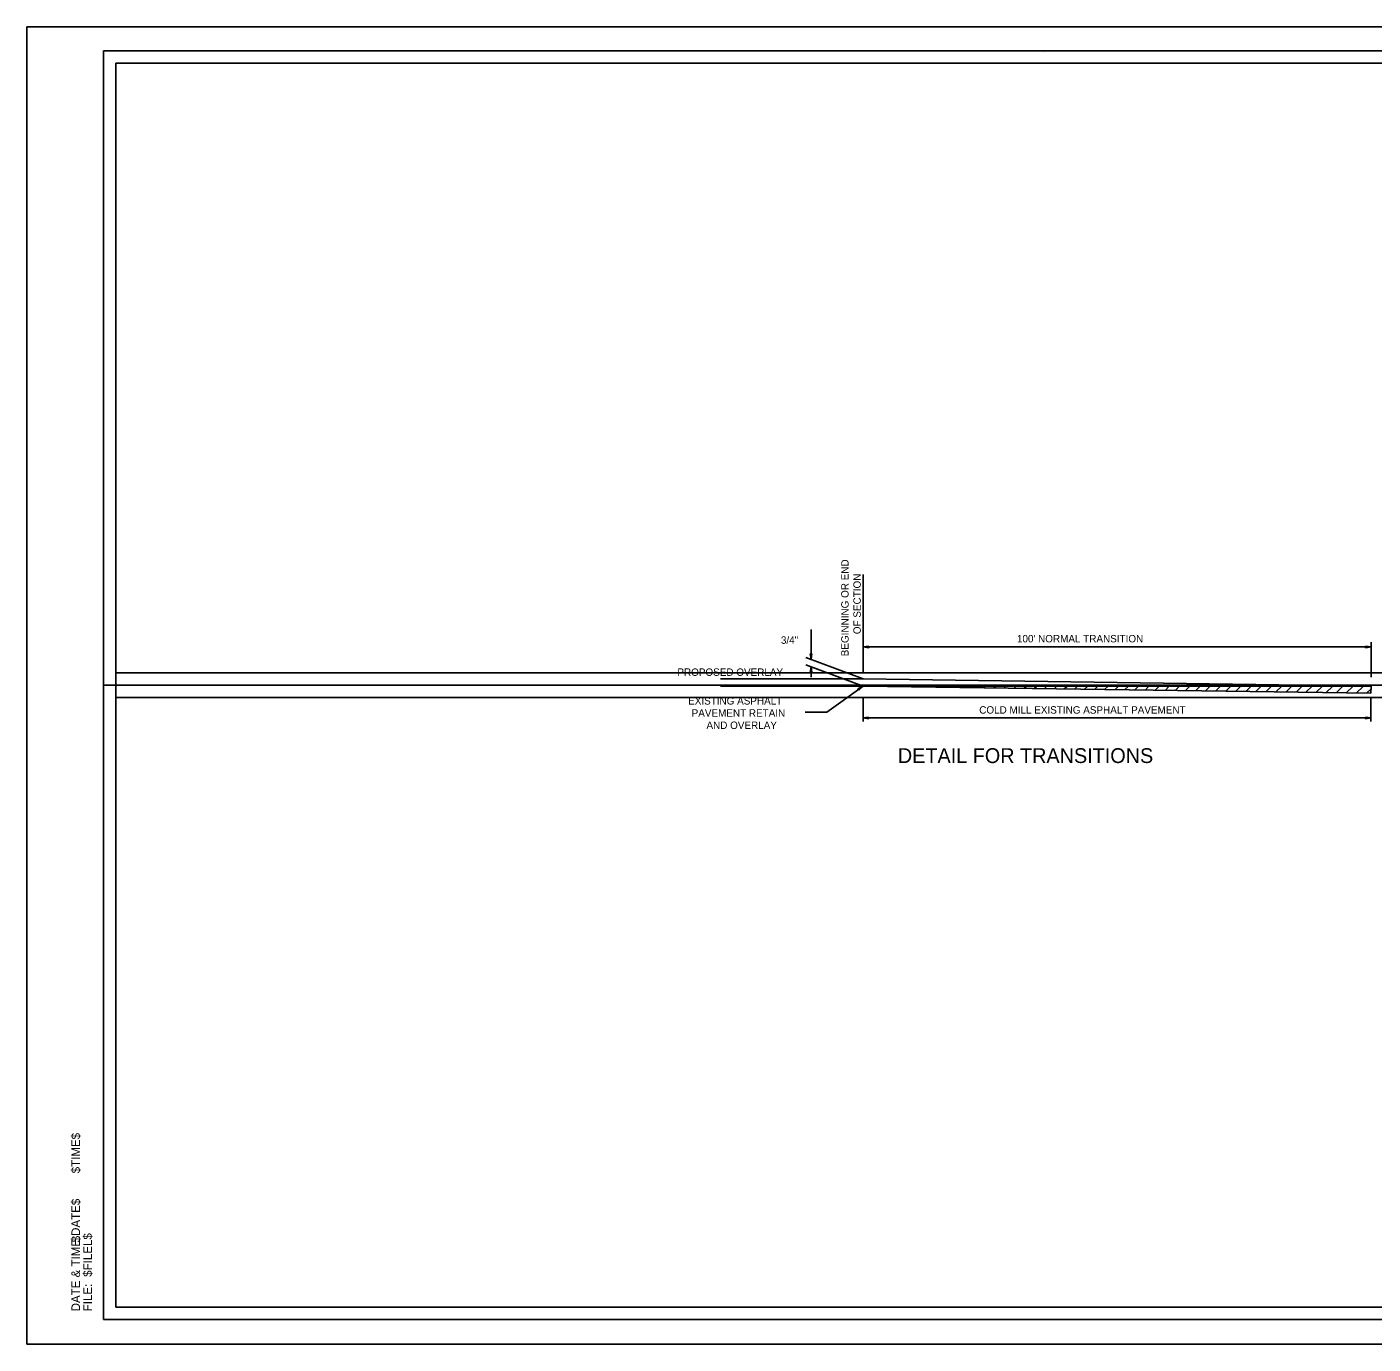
# Model space of a CAD drawing. Extents: x -12 to 321, y -4 to 209.
# Drawn here: x -12.4 to 205.7, y -4 to 209.4 of the extents above; entities that cross this region are included whole.
import ezdxf

# ---------------------------------------------------------------- set-up
doc = ezdxf.new("R2010")
doc.units = 0
for name, color, linetype in [('Default', 7, 'Continuous'), ('R_Border', 7, 'Continuous'), ('R_Border Notes', 7, 'Continuous'), ('R_Border Plan-Plan', 7, 'Continuous'), ('R_No Plot', 7, 'Continuous')]:
    doc.layers.add(name, color=color, linetype=linetype)

msp = doc.modelspace()

# ---------------------------------------------------------------- linework, layer by layer
at = {"layer": 'Default'}
for p, q in [((123.07, 104.67), (123.07, 120.64)), ((114.63, 106.94), (114.63, 111.74)), ((124, 109.07), (123.07, 108.94)), ((124, 108.8), (124, 109.07)), ((204.44, 109.07), (205.38, 108.94)), ((204.44, 109.07), (204.44, 108.8)), ((205.38, 104.05), (205.38, 109.73)), ((123.07, 103.74), (113.79, 107.2)), ((114.5, 107.83), (114.63, 106.94)), ((114.5, 107.83), (114.63, 107.07)), ((114.76, 107.83), (114.5, 107.83)), ((114.54, 107.83), (114.63, 107.25)), ((114.54, 107.83), (114.63, 107.38)), ((114.59, 107.83), (114.63, 107.56)), ((114.59, 107.83), (114.63, 107.69)), ((114.76, 107.83), (114.63, 106.94)), ((114.67, 107.83), (114.63, 107.56)), ((114.72, 107.83), (114.63, 107.25)), ((114.72, 107.83), (114.63, 107.07)), ((114.67, 107.83), (114.63, 107.38)), ((114.63, 107.83), (114.63, 107.69)), ((123.07, 108.94), (205.38, 108.94)), ((124, 108.8), (123.07, 108.94)), ((124, 109.03), (123.2, 108.94)), ((124, 108.8), (123.2, 108.94)), ((124, 109.03), (123.38, 108.94)), ((124, 108.85), (123.38, 108.94)), ((124, 108.98), (123.56, 108.94)), ((124, 108.85), (123.56, 108.94)), ((124, 108.98), (123.69, 108.94)), ((124, 108.89), (123.69, 108.94)), ((124, 108.94), (123.87, 108.94)), ((124, 108.89), (123.87, 108.94)), ((204.44, 109.03), (205.07, 108.94)), ((204.44, 109.03), (205.2, 108.94)), ((204.44, 108.98), (204.76, 108.94)), ((204.44, 108.98), (204.89, 108.94)), ((204.44, 108.8), (205.38, 108.94)), ((204.44, 108.89), (204.76, 108.94)), ((204.44, 108.85), (205.07, 108.94)), ((204.44, 108.8), (205.2, 108.94)), ((204.44, 108.85), (204.89, 108.94)), ((204.44, 108.89), (204.58, 108.94)), ((204.44, 108.94), (204.58, 108.94)), ((123.07, 102.59), (113.79, 106.05)), ((114.5, 104.8), (114.63, 105.74)), ((114.5, 104.8), (114.63, 105.6)), ((114.5, 104.8), (114.76, 104.8)), ((114.54, 104.8), (114.63, 105.43)), ((114.54, 104.8), (114.63, 105.3)), ((114.59, 104.8), (114.63, 105.12)), ((114.59, 104.8), (114.63, 104.94)), ((114.76, 104.8), (114.63, 105.74)), ((114.63, 104.05), (114.63, 105.74)), ((114.72, 104.8), (114.63, 105.6)), ((114.72, 104.8), (114.63, 105.43)), ((114.67, 104.8), (114.63, 105.3)), ((114.67, 104.8), (114.63, 105.12)), ((114.63, 104.8), (114.63, 104.94)), ((99.97, 103.74), (123.07, 103.74)), ((99.97, 102.58), (205.38, 102.58)), ((117.21, 98.37), (123.07, 102.59)), ((122.23, 102.14), (123.07, 102.59)), ((122.4, 101.92), (123.07, 102.59)), ((205.38, 102.59), (123.07, 103.74)), ((205.33, 101.43), (123.07, 102.59)), ((126.31, 102.54), (126.36, 102.59)), ((127.93, 102.52), (128, 102.59)), ((129.55, 102.49), (129.69, 102.59)), ((131.21, 102.47), (131.33, 102.59)), ((132.84, 102.45), (132.97, 102.59)), ((134.46, 102.42), (134.62, 102.59)), ((136.08, 102.4), (136.26, 102.59)), ((137.74, 102.38), (137.95, 102.59)), ((139.36, 102.36), (139.59, 102.59)), ((141.03, 102.33), (141.24, 102.59)), ((142.61, 102.31), (142.88, 102.59)), ((144.27, 102.29), (144.57, 102.59)), ((145.89, 102.26), (146.21, 102.59)), ((147.55, 102.24), (147.86, 102.59)), ((149.13, 102.22), (149.54, 102.59)), ((150.8, 102.2), (151.19, 102.59)), ((152.42, 102.17), (152.83, 102.59)), ((154.04, 102.15), (154.48, 102.58)), ((155.66, 102.13), (156.16, 102.59)), ((157.33, 102.1), (157.8, 102.59)), ((158.95, 102.08), (159.45, 102.59)), ((160.57, 102.06), (161.09, 102.59)), ((162.19, 102.04), (162.78, 102.59)), ((163.85, 102.01), (164.42, 102.59)), ((165.43, 101.99), (166.07, 102.59)), ((167.09, 101.97), (167.71, 102.59)), ((168.76, 101.94), (169.35, 102.59)), ((170.38, 101.92), (171.04, 102.59)), ((172, 101.9), (172.68, 102.59)), ((173.62, 101.87), (174.33, 102.59)), ((175.29, 101.85), (176.02, 102.59)), ((176.91, 101.83), (177.66, 102.59)), ((178.53, 101.8), (179.3, 102.59)), ((180.15, 101.78), (180.95, 102.59)), ((181.81, 101.76), (182.63, 102.59)), ((183.39, 101.74), (184.28, 102.59)), ((185.05, 101.71), (185.92, 102.59)), ((186.68, 101.69), (187.57, 102.59)), ((188.34, 101.67), (189.21, 102.59)), ((189.91, 101.64), (190.9, 102.59)), ((191.58, 101.62), (192.54, 102.59)), ((193.21, 101.61), (194.19, 102.59)), ((194.82, 101.58), (195.83, 102.59)), ((196.44, 101.55), (197.52, 102.59)), ((198.11, 101.53), (199.16, 102.59)), ((199.73, 101.51), (200.8, 102.59)), ((201.35, 101.48), (202.45, 102.59)), ((202.97, 101.46), (204.14, 102.59)), ((205.38, 102.59), (205.33, 101.43)), ((122.23, 102.14), (122.4, 101.92)), ((122.27, 102.14), (122.94, 102.5)), ((122.27, 102.14), (122.8, 102.41)), ((122.27, 102.1), (122.67, 102.32)), ((122.27, 102.1), (122.58, 102.23)), ((122.32, 102.05), (122.45, 102.14)), ((122.32, 102.05), (122.45, 102.14)), ((122.36, 101.96), (122.8, 102.41)), ((122.36, 102.01), (122.67, 102.32)), ((122.36, 102.01), (122.58, 102.23)), ((122.4, 101.96), (122.94, 102.5)), ((123.07, 96.85), (123.07, 100.85)), ((204.63, 101.44), (205.36, 102.17)), ((205.33, 96.85), (205.33, 100.85)), ((113.7, 98.37), (117.21, 98.37)), ((123.96, 97.56), (123.07, 97.43)), ((123.96, 97.56), (123.07, 97.43)), ((205.33, 97.43), (123.07, 97.43)), ((123.96, 97.3), (123.07, 97.43)), ((123.96, 97.3), (123.07, 97.43)), ((123.96, 97.56), (123.2, 97.43)), ((123.96, 97.56), (123.2, 97.43)), ((123.96, 97.34), (123.2, 97.43)), ((123.96, 97.34), (123.2, 97.43)), ((123.96, 97.52), (123.38, 97.43)), ((123.96, 97.52), (123.38, 97.43)), ((123.96, 97.34), (123.38, 97.43)), ((123.96, 97.34), (123.38, 97.43)), ((123.96, 97.52), (123.51, 97.43)), ((123.96, 97.52), (123.51, 97.43)), ((123.96, 97.39), (123.51, 97.43)), ((123.96, 97.39), (123.51, 97.43)), ((123.96, 97.47), (123.69, 97.43)), ((123.96, 97.47), (123.69, 97.43)), ((123.96, 97.39), (123.69, 97.43)), ((123.96, 97.39), (123.69, 97.43)), ((123.96, 97.47), (123.83, 97.43)), ((123.96, 97.47), (123.83, 97.43)), ((123.96, 97.43), (123.83, 97.43)), ((123.96, 97.43), (123.83, 97.43)), ((123.96, 97.3), (123.96, 97.56)), ((123.96, 97.3), (123.96, 97.56)), ((204.44, 97.56), (205.33, 97.43)), ((204.44, 97.56), (205.2, 97.43)), ((204.44, 97.56), (204.44, 97.3)), ((204.44, 97.52), (205.02, 97.43)), ((204.44, 97.52), (204.89, 97.43)), ((204.44, 97.47), (204.71, 97.43)), ((204.44, 97.47), (204.58, 97.43)), ((204.44, 97.3), (205.33, 97.43)), ((204.44, 97.39), (204.71, 97.43)), ((204.44, 97.34), (205.02, 97.43)), ((204.44, 97.34), (205.2, 97.43)), ((204.44, 97.39), (204.89, 97.43)), ((204.44, 97.43), (204.58, 97.43))]:
    msp.add_line(p, q, dxfattribs=at)
at = {"layer": 'R_Border'}
for p, q in [((0, 205.46), (316.18, 205.46)), ((0, 0), (0, 205.46)), ((152.52, 205.2), (152.52, 205.2)), ((152.52, 205.2), (152.52, 205.2)), ((0, 0), (0, 0)), ((316.18, 0), (0, 0))]:
    msp.add_line(p, q, dxfattribs=at)
at = {"layer": 'R_Border Plan-Plan'}
msp.add_line((0, 102.73), (316.18, 102.73), dxfattribs=at)
at = {"layer": 'R_No Plot'}
for points in [[(-12.41, 209.35), (320.93, 209.35), (320.93, -3.98), (-12.41, -3.98)], [(314.18, 104.73), (2, 104.73), (2, 203.46), (251.54, 203.46), (251.54, 193.58), (269.08, 193.58), (293.18, 193.58), (293.18, 171.25), (314.18, 171.25)], [(2, 203.46), (251.54, 203.46), (251.54, 193.58), (269.08, 193.58), (293.18, 193.58), (293.18, 171.25), (314.18, 171.25), (314.18, 2), (2, 2)], [(2, 100.73), (314.18, 100.73), (314.18, 2), (2, 2)]]:
    msp.add_lwpolyline(points, close=True, dxfattribs=at)

# ---------------------------------------------------------------- texts
at = {"layer": 'Default'}
for s, p in [('BEGINNING OR END', (120.72, 107.42)), ('OF SECTION', (122.69, 111))]:
    msp.add_text(s, height=1.2, rotation=90, dxfattribs=at).set_placement(p)
for s, height, p in [('3/4"', 1.2, (109.75, 109.44)), ("100' NORMAL TRANSITION", 1.2, (147.99, 109.67)), ('PROPOSED OVERLAY', 1.2, (92.98, 104.25)), ('EXISTING ASPHALT', 1.2, (94.72, 99.6)), ('PAVEMENT RETAIN', 1.2, (95.29, 97.63)), ('COLD MILL EXISTING ASPHALT PAVEMENT', 1.2, (141.88, 98.13)), ('AND OVERLAY', 1.2, (97.69, 95.65)), ('DETAIL FOR TRANSITIONS', 2.4, (128.7, 90.13))]:
    msp.add_text(s, height=height, dxfattribs=at).set_placement(p)
at = {"layer": 'R_Border Notes'}
for s, height, p in [('$TIME$', 1.397, (-3.8, 23.67)), ('$DATE$', 1.397, (-3.8, 12.5)), ('DATE & TIME:', 1.3968, (-3.8, 1.32)), ('$FILEL$', 1.397, (-1.88, 6.91)), ('FILE: ', 1.397, (-1.88, 1.32))]:
    msp.add_text(s, height=height, rotation=90, dxfattribs=at).set_placement(p)

doc.saveas('drawing.dxf')
